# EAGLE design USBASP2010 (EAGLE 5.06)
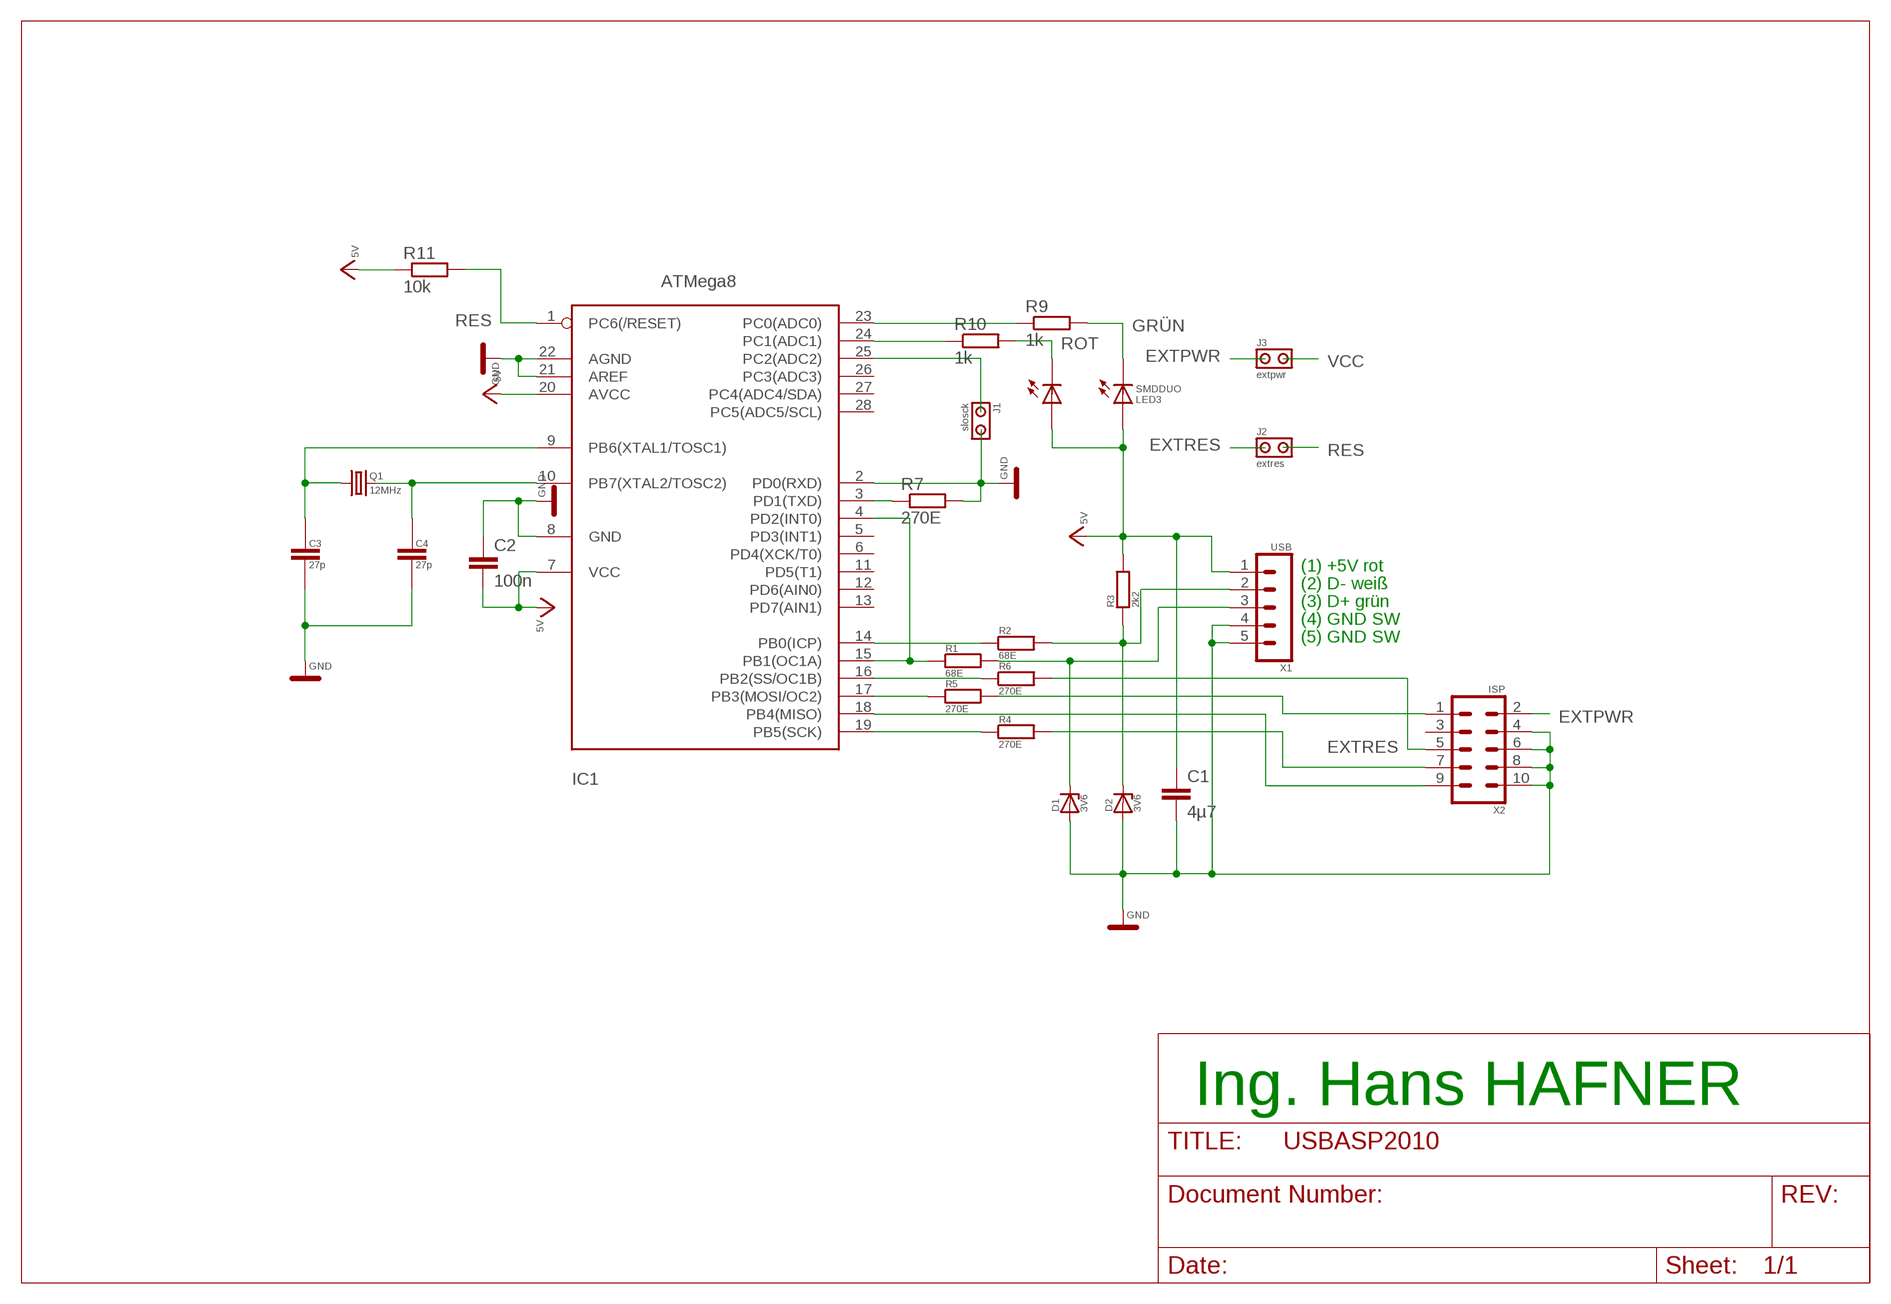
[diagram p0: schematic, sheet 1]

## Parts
C1  4µ7  C-EUC1206  [C1206]
C2  100n  C-EUC1206  [C1206]
C3  27p  C_KERKO_RM0254  [C_KERKO_RM0254]
C4  27p  C_KERKO_RM0254  [C_KERKO_RM0254]
D1  3V6  D_BZX55_DO35-7  [D_ZD_DO35-7]
D2  3V6  D_BZX55_DO35-7  [D_ZD_DO35-7]
IC1  ATMega8  MEGA8-P  [DIL28-3]
J1  slosck  X_PINHEAD2_HORI  [X_PINHEAD2_HORI]
J2  extres  X_PINHEAD2_HORI  [X_PINHEAD2_HORI]
J3  extpwr  X_PINHEAD2_HORI  [X_PINHEAD2_HORI]
LED3  SMDDUO  LED_DUOLED_SMD_  [LED_DUOLED_SMD_]
Q1  12MHz  Q_QUARZ_HC49S  [Q_QUARZ_HC49S_]
R1  68E  R_H0204_RM0762  [R_H0204_RM0762]
R2  68E  R_H0204_RM0762  [R_H0204_RM0762]
R3  2k2  R_H0204_RM0762  [R_H0204_RM0762]
R4  270E  R_H0204_RM0762  [R_H0204_RM0762]
R5  270E  R_H0204_RM0762  [R_H0204_RM0762]
R6  270E  R_H0204_RM0762  [R_H0204_RM0762]
R7  270E  R-EU_R1206  [R1206]
R9  1k  R-EU_R1206  [R1206]
R10  1k  R-EU_R1206  [R1206]
R11  10k  R-EU_R1206  [R1206]
X1  USB  X_NSL25-5W  [X_NSL25-5W]
X2  ISP  X_HARTING_ML10P  [X_HARTING_ML10P_]

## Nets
EXTPWR: J3.1 X2.2
EXTRES: J2.1 R6.2 X2.5
GND: C1.2 C2.1 C3.2 C4.2 D1.A D2.A IC1.2(PD0(RXD)) IC1.8(GND) IC1.21(AREF) IC1.22(AGND) J1.2 R7.2 X1.4 X1.5 X2.4 X2.6 X2.8 X2.10
GRÜN: LED3.3 R9.2
N$1: R5.2 X2.1
N$4: R4.2 X2.7
N$5: IC1.18(PB4(MISO)) X2.9
N$6: IC1.3(PD1(TXD)) R7.1
N$7: IC1.16(PB2(SS/OC1B)) R6.1
N$8: IC1.17(PB3(MOSI/OC2)) R5.1
N$9: D2.C R2.2 R3.1 X1.2
N$10: D1.C R1.2 X1.3
N$11: IC1.4(PD2(INT0)) IC1.15(PB1(OC1A)) R1.1
N$12: IC1.14(PB0(ICP)) R2.1
N$14: IC1.24(PC1(ADC1)) R10.1
N$15: IC1.23(PC0(ADC0)) R9.1
N$19: C3.1 IC1.9(PB6(XTAL1/TOSC1)) Q1.1
N$20: C4.1 IC1.10(PB7(XTAL2/TOSC2)) Q1.2
N$21: IC1.19(PB5(SCK)) R4.1
RES: IC1.1(PC6(/RESET)) J2.2 R11.2
ROT: LED3.4 R10.2
SLOWSCK: IC1.25(PC2(ADC2)) J1.1
VCC: C1.1 C2.2 IC1.7(VCC) IC1.20(AVCC) J3.2 LED3.1 LED3.2 R3.2 R11.1 X1.1 ; supply symbol labelled 5V
Unconnected: IC1.5(PD3(INT1)) IC1.6(PD4(XCK/T0)) IC1.11(PD5(T1)) IC1.12(PD6(AIN0)) IC1.13(PD7(AIN1)) IC1.26(PC3(ADC3)) IC1.27(PC4(ADC4/SDA)) IC1.28(PC5(ADC5/SCL)) X2.3

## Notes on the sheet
- (1) +5V rot
- (2) D- weiß
- (3) D+ grün
- (4) GND SW
- (5) GND SW
- Ing. Hans HAFNER

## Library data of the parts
C1 C2 = rcl:C-EU: CAPACITOR, European symbol
C3 C4 = 0HDM2007:C_KERKO_*: Keramikkondensatoren
D1 D2 = 0HDM2007:D_BZX55_*: Z-Diode
IC1 = avr:MEGA8-P: MICROCONTROLLER 8 Kbytes FLASH 1 kbytes SRAM 512 bytes EEPROM USART 4-channel 10 bit ADC 2-channel 8 bit ADC
J1-J3 = 0HDM2007:X_PINHEAD2_: PinHead 2
LED3 = 0HDM2007:LED_DUOLED_SMD_
Q1 = 0HDM2007:Q_QUARZ_: Schwingquarz
R1-R6 = 0HDM2007:R_*: Widerstände
R7 R9-R11 = rcl:R-EU_: RESISTOR, European symbol
X1 = 0HDM2007:X_NSL25-5: Nylonstiftleiste 5polig RM0254 Created by HDM 17/01/2007
X2 = 0HDM2007:X_HARTING_ML10: HARTING Wannensteckerleiste 10polig (5x2)

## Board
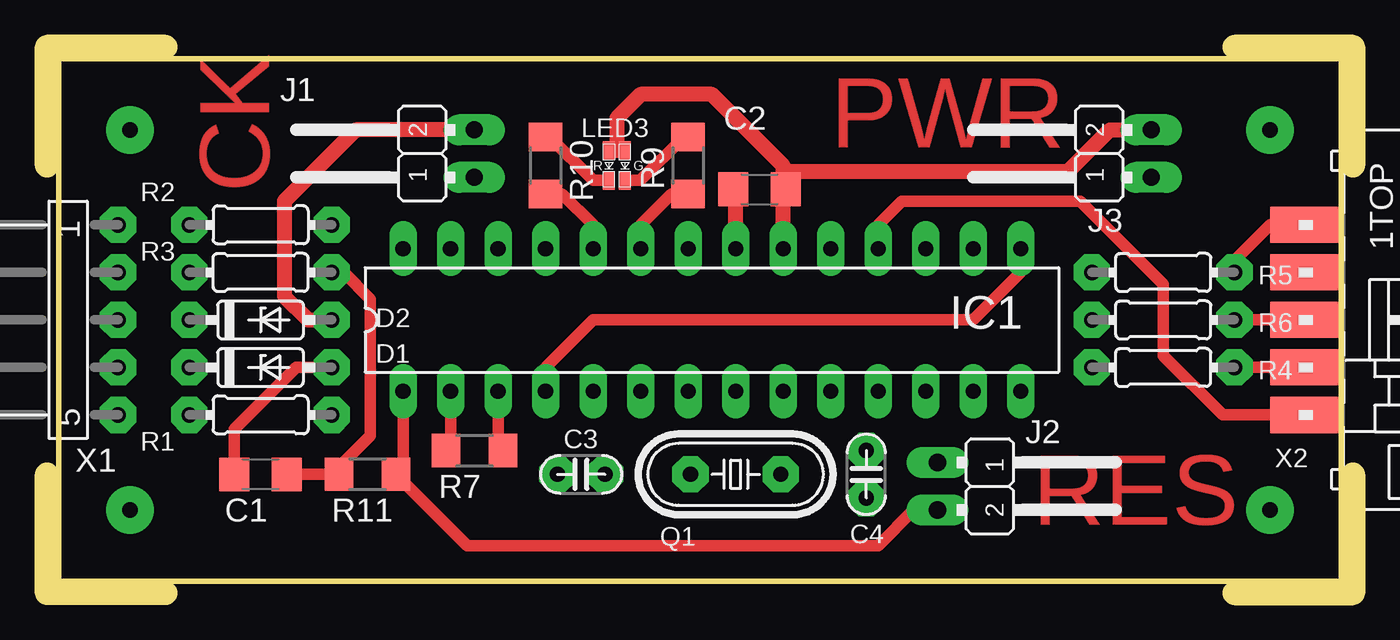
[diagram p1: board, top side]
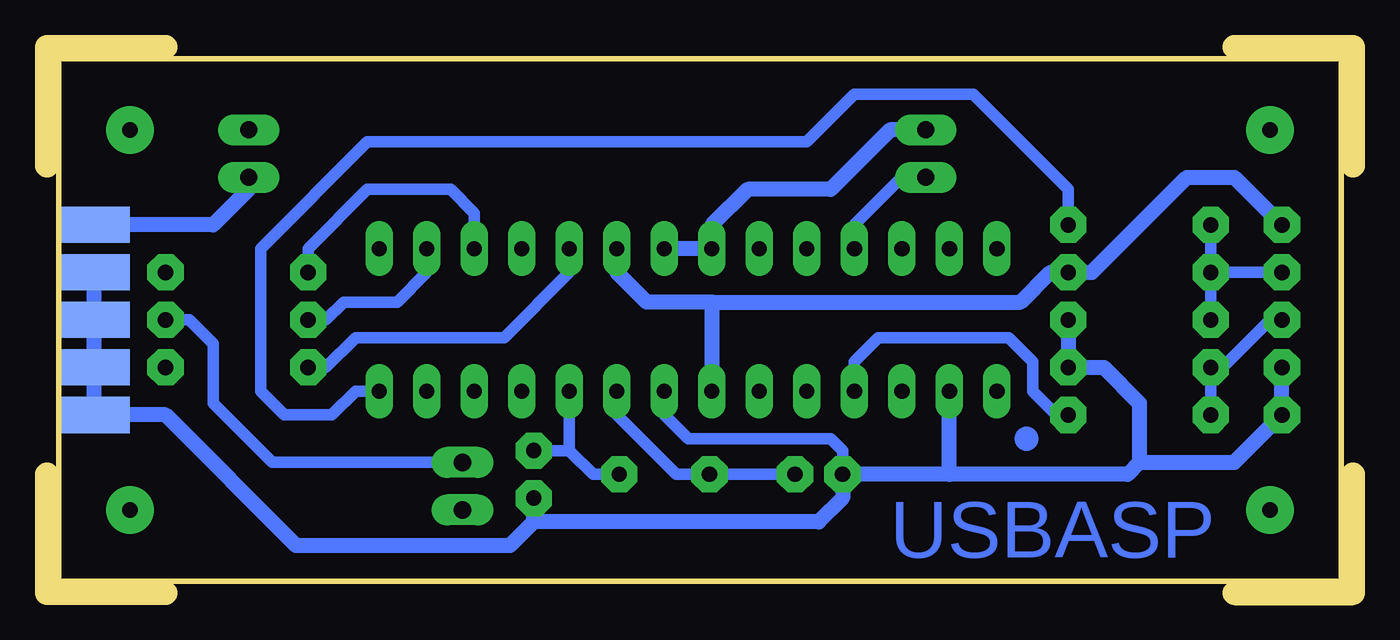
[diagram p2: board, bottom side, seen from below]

Size 69.85 x 29.21 mm. Coordinates in mm from the lower left corner, seen from the top.
Outline: 0,6.35 0,0 6.35,0
Outline: 0,22.86 0,29.21 6.35,29.21
Outline: 63.5,29.21 69.85,29.21 69.85,22.86
Outline: 69.85,6.35 69.85,0 63.5,0
Outline: 0.63,28.58 0.63,0.63 69.22,0.63 69.22,28.58 0.63,28.58
Copper layers (1*16): Top 0.035mm / dielectric 1.5mm / Bottom 0.035mm
Design rules "HTL-default *": minimum track width 24mil, minimum drill 32mil, track to track 24mil, track to pad 24mil, pad to pad 24mil, via to via 24mil, smd to smd 12mil, copper to edge 40mil, drill to drill 24mil, minimum pad ring 10mil, minimum via ring 16mil, stop-mask expansion 4mil, vias tented up to drill 0mil, thermal gap 16mil

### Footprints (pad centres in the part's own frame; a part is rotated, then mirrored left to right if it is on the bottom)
C1206 = smd 1.6 x 1.8: 1 -1.4,0; 2 1.4,0
C_KERKO_RM0254 = drill 0.813 pad 1.93 octagon: 1 -1.27,0; 2 1.27,0
D_ZD_DO35-7 = drill 0.813 pad 1.93 octagon: A 3.81,0; C -3.81,0
DIL28-3 = drill 0.813 long: 1 -16.51,-3.81; 2 -13.97,-3.81; 3 -11.43,-3.81; 4 -8.89,-3.81; 5 -6.35,-3.81; 6 -3.81,-3.81; 7 -1.27,-3.81; 8 1.27,-3.81; 9 3.81,-3.81; 10 6.35,-3.81; 11 8.89,-3.81; 12 11.43,-3.81; 13 13.97,-3.81; 14 16.51,-3.81; 15 16.51,3.81; 16 13.97,3.81; 17 11.43,3.81; 18 8.89,3.81; 19 6.35,3.81; 20 3.81,3.81; 21 1.27,3.81; 22 -1.27,3.81; 23 -3.81,3.81; 24 -6.35,3.81; 25 -8.89,3.81; 26 -11.43,3.81; 27 -13.97,3.81; 28 -16.51,3.81
X_PINHEAD2_HORI = drill 0.914 long: 1 -1.27,-1.27; 2 1.27,-1.27
LED_DUOLED_SMD_ = smd 0.65 x 1: 1 0.425,0.8; 2 -0.425,0.8; 3 0.425,-0.8; 4 -0.425,-0.8
Q_QUARZ_HC49S_ = drill 0.813 pad 1.93 octagon: 1 -2.413,0; 2 2.413,0
R_H0204_RM0762 = drill 0.813 pad 1.93 octagon: 1 -3.81,0; 2 3.81,0
R1206 = smd 1.524 x 1.778: 1 -1.524,0; 2 1.524,0
X_NSL25-5W = drill 0.813 pad 1.93 octagon: 1 -5.08,2.54; 2 -2.54,2.54; 3 0,2.54; 4 2.54,2.54; 5 5.08,2.54
X_HARTING_ML10P_ = smd 1.93 x 3.81: 1 -5.08,0; 3 -2.54,0; 5 0,0; 7 2.54,0; 9 5.08,0 | smd 1.93 x 3.81 bottom: 2 -5.08,0; 4 -2.54,0; 6 0,0; 8 2.54,0; 10 5.08,0

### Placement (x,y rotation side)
C1  11.43,6.35 180 top
C2  38.1,21.59 0 top
C3  28.57,6.35 180 top
C4  43.81,6.35 270 top
D1  11.43,12.07 0 top
D2  11.43,14.61 0 top
IC1  35.56,14.61 0 top
J1  21.59,23.5 90 top
J2  48.89,5.71 270 top
J3  57.78,23.5 90 top
LED3  30.48,22.86 0 top
Q1  36.83,6.35 0 top
R1  11.43,9.53 180 top
R2  11.43,19.69 180 top
R3  11.43,17.14 0 top
R4  59.69,12.07 0 top
R5  59.69,17.14 0 top
R6  59.69,14.61 0 top
R7  22.86,7.62 180 top
R9  34.29,22.86 90 top
R10  26.67,22.86 90 top
R11  17.14,6.35 0 top
X1  1.27,14.61 270 top
X2  67.31,14.61 270 top

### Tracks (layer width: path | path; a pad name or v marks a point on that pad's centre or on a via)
EXTPWR
  Bottom 0.813: X2.2 60.96,19.69 59.05,21.59 J3.1
EXTRES
  Top 0.61: X2.5 | R6.2 X2.5
  Bottom 0.61: R6.2 62.23,14.61 60.96,13.34 60.96,10.16 57.78,6.99 J2.1
GND
  Top 0.61: IC1.2 21.59,7.62 R7.2 | C1.2 10.03,8.76 13.33,12.07 D1.A
  Top 0.813: C2.1 36.83,21.59 IC1.21 | J1.2 16.51,24.77 12.7,20.95 12.7,15.88 13.97,14.61 D2.A
  Bottom 0.61: IC1.8 36.83,9.53 35.56,8.26 27.94,8.26 27.3,7.62 C3.2
  Bottom 0.813: X1.4 X1.5 6.35,6.99 11.43,6.99 | X2.4 X2.6 X2.8 X2.10 63.5,9.53 56.52,2.54 45.08,2.54 43.81,3.81 | D2.A D1.A 13.33,12.07 11.43,10.16 11.43,6.99 | J1.2 24.76,24.77 27.94,21.59 32.38,21.59 34.29,19.69 IC1.22 IC1.21 | 11.43,6.99 12.06,6.35 21.59,6.35 | 21.59,6.35 IC1.2 | 21.59,6.35 C3.2 27.3,5.08 28.57,3.81 43.81,3.81 | 43.81,3.81 C4.2
GRÜN
  Top 0.61: LED3.3 31.74,22.06 34.07,24.38 R9.2
N$1
  Top 0.61: X2.1 65.41,19.69 63.5,17.78 R5.2
N$2  (via drill 0.81 pad 2.54)
  other vias: 4.44,24.77
N$3  (via drill 0.81 pad 2.54)
  other vias: 4.44,4.45
N$4
  Top 0.61: R4.2 X2.7 | R4.2
N$5
  Top 0.61: X2.9 | IC1.18 44.45,19.69 45.72,20.95 55.24,20.95 59.69,16.51 59.69,12.7 62.86,9.53 X2.9
N$6
  Top 0.61: IC1.3 24.13,7.62 R7.1
N$7
  Bottom 0.61: IC1.16 49.53,17.14 51.12,15.56 53.97,15.56 54.93,14.61 R6.1
N$8
  Bottom 0.61: IC1.17 46.99,20.32 48.26,21.59 52.7,21.59 55.88,18.41 R5.1
N$9
  Bottom 0.61: R3.1 X1.2 | R2.2 R3.1 | R3.1 D2.C
N$10
  Bottom 0.61: X1.3 4.44,14.61 6.98,12.07 D1.C R1.2
N$11
  Top 0.61: IC1.4 26.67,12.07 29.21,14.61 49.53,14.61 52.07,17.14 IC1.15
  Bottom 0.61: IC1.4 26.67,12.38 25.4,13.65 18.41,13.65 17.14,12.38 17.14,10.79 15.87,9.53 R1.1
N$12
  Bottom 0.61: IC1.14 53.34,10.79 54.61,9.53 57.15,9.53 58.42,10.79 58.42,18.41 52.7,24.13 29.21,24.13 26.67,26.67 20.32,26.67 15.24,21.59 R2.1
N$13  (via drill 0.81 pad 2.54)
  other vias: 65.41,24.77
N$14
  Top 0.61: R10.1 27.56,21.34 29.21,19.69 IC1.24
N$15
  Top 0.61: R9.1 33.4,21.34 31.75,19.69 IC1.23
N$16  (via drill 0.81 pad 2.54)
  other vias: 65.41,4.45
N$19
  Bottom 0.61: IC1.9 39.37,9.53 36.2,6.35 Q1.1 C3.1
N$20
  Bottom 0.61: Q1.2 40.64,6.35 41.91,7.62 | 41.91,7.62 C4.1 | 41.91,7.62 IC1.10
N$21
  Bottom 0.61: IC1.19 41.91,17.14 45.4,13.65 53.34,13.65 54.93,12.07 R4.1
RES
  Top 0.61: J2.2 46.35,4.45 44.45,2.54 22.48,2.54 R11.2 19.05,6.35 IC1.1
ROT
  Top 0.61: LED3.4 29.22,22.06 26.89,24.38 R10.2
SLOWSCK
  Bottom 0.61: J1.1 24.13,22.23 26.67,19.69 IC1.25
VCC
  Top 0.61: C1.1 R11.1 15.62,6.73 17.3,8.41 17.3,15.72 15.87,17.14 R3.2 | LED3.1 30.48,23.66 LED3.2
  Top 0.813: 30.48,23.66 30.48,25.4 31.75,26.67 35.56,26.67 39.37,22.86 39.37,22.54 | IC1.20 39.37,21.59 C2.2 39.37,21.72 39.37,22.54 | J3.2 56.83,24.77 54.61,22.54 39.37,22.54
  Bottom 0.813: IC1.20 39.37,17.14 37.78,15.56 34.29,15.56 | 34.29,15.56 17.78,15.56 16.19,17.14 R3.2 13.97,17.14 8.89,22.23 6.35,22.23 X1.1 | 34.29,15.56 IC1.7
(copper drawn outside any net)
  shapes: Bottom circle x1

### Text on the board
Top: PWR | CK | RES
Bottom: USBASP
